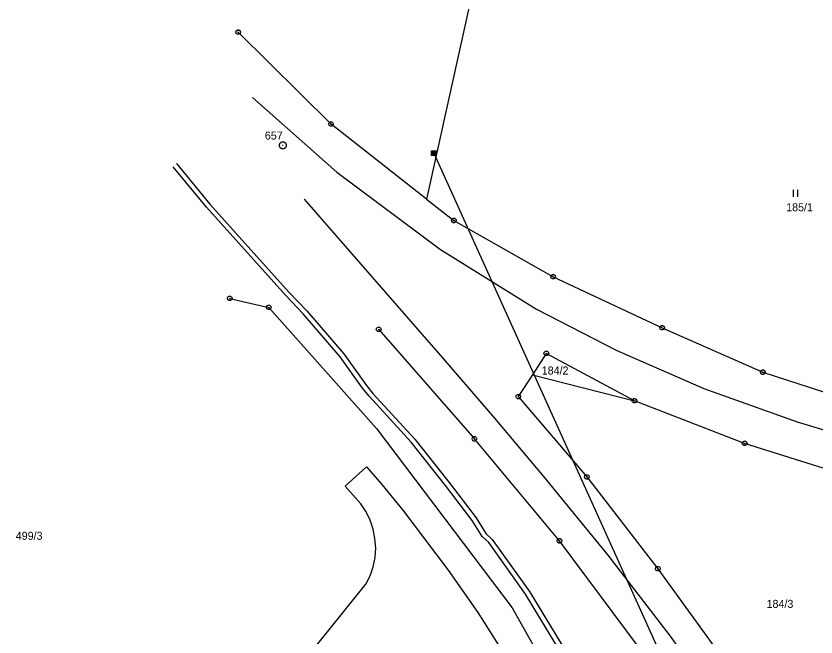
# Model space of a CAD drawing. Extents: x -755359 to -754474, y -1162585 to -1161655.
# Drawn here: x -755334.3 to -755164.4, y -1162276.2 to -1162144.3 of the extents above; entities that cross this region are included whole.
import ezdxf

# ---------------------------------------------------------------- set-up
doc = ezdxf.new("R2010")
doc.units = 0
for name, color, linetype in [('Vrstva 1', 7, 'Continuous'), ('Vrstva 13', 7, 'Continuous'), ('Vrstva 2', 7, 'Continuous'), ('Vrstva 3', 7, 'Continuous'), ('Vrstva 6', 7, 'Continuous'), ('Vrstva 8', 7, 'Continuous')]:
    doc.layers.add(name, color=color, linetype=linetype)

msp = doc.modelspace()

# ---------------------------------------------------------------- linework, layer by layer
at = {"layer": 'Vrstva 1'}
for p, q in [((-755230.33, -1162107.53), (-755247.11, -1162183.21)), ((-755267.37, -1162167.29), (-755287.08, -1162147.76)), ((-755287.08, -1162147.76), (-755287.08, -1162147.76)), ((-755247.11, -1162183.21), (-755267.37, -1162167.29)), ((-755247.11, -1162183.21), (-755241.3, -1162187.77)), ((-755241.3, -1162187.77), (-755220.18, -1162199.71)), ((-755220.18, -1162199.71), (-755197.03, -1162210.54)), ((-755288.88, -1162204.3), (-755288.88, -1162204.3)), ((-755288.88, -1162204.3), (-755280.59, -1162206.21)), ((-755257.72, -1162231.95), (-755280.59, -1162206.21)), ((-755280.59, -1162206.21), (-755280.59, -1162206.21)), ((-755257.25, -1162210.88), (-755257.25, -1162210.88)), ((-755257.25, -1162210.88), (-755255.8, -1162212.54)), ((-755197.03, -1162210.54), (-755175.66, -1162219.97)), ((-755255.8, -1162212.54), (-755236.92, -1162234.12)), ((-755221.65, -1162215.97), (-755224.59, -1162220.51)), ((-755202.91, -1162226.05), (-755221.65, -1162215.97)), ((-755224.59, -1162220.51), (-755227.6, -1162225.16)), ((-755224.59, -1162220.51), (-755202.91, -1162226.05)), ((-755175.66, -1162219.97), (-755153.09, -1162227.31)), ((-755227.6, -1162225.16), (-755213.03, -1162242.21)), ((-755179.53, -1162235.08), (-755202.91, -1162226.05)), ((-755257.72, -1162231.95), (-755228.92, -1162270)), ((-755218.86, -1162255.78), (-755236.92, -1162234.12)), ((-755156.59, -1162242.36), (-755179.53, -1162235.08)), ((-755264.36, -1162244.17), (-755259.86, -1162240.09)), ((-755259.86, -1162240.09), (-755256.55, -1162243.81)), ((-755213.03, -1162242.21), (-755197.95, -1162261.69)), ((-755261.07, -1162247.95), (-755264.36, -1162244.17)), ((-755256.55, -1162243.81), (-755252.15, -1162249.27)), ((-755259.94, -1162249.61), (-755261.07, -1162247.95)), ((-755259.06, -1162251.4), (-755259.94, -1162249.61)), ((-755252.15, -1162249.27), (-755242.47, -1162262.02)), ((-755258.42, -1162253.32), (-755259.06, -1162251.4)), ((-755258.04, -1162255.29), (-755258.42, -1162253.32)), ((-755257.86, -1162257.3), (-755258.04, -1162255.29)), ((-755201.65, -1162278.82), (-755218.86, -1162255.78)), ((-755258.01, -1162259.3), (-755257.86, -1162257.3)), ((-755258.42, -1162261.28), (-755258.01, -1162259.3)), ((-755259.05, -1162263.18), (-755258.42, -1162261.28)), ((-755242.47, -1162262.02), (-755236.16, -1162271.02)), ((-755197.95, -1162261.69), (-755179.66, -1162287.01)), ((-755259.96, -1162264.99), (-755259.05, -1162263.18)), ((-755273.15, -1162281.3), (-755259.96, -1162264.99)), ((-755228.92, -1162270), (-755211.8, -1162300.42)), ((-755236.16, -1162271.02), (-755230.79, -1162279.46))]:
    msp.add_line(p, q, dxfattribs=at)
at = {"layer": 'Vrstva 13'}
for p, q in [((-755293.84, -1162184.94), (-755300.91, -1162176.35)), ((-755300.91, -1162176.35), (-755300.91, -1162176.35)), ((-755300.17, -1162175.67), (-755300.17, -1162175.67)), ((-755300.17, -1162175.67), (-755293.08, -1162184.3)), ((-755276.95, -1162203.71), (-755293.84, -1162184.94)), ((-755293.08, -1162184.3), (-755276.23, -1162203.03)), ((-755273.27, -1162207.6), (-755276.95, -1162203.71)), ((-755276.23, -1162203.03), (-755272.53, -1162206.94)), ((-755265.46, -1162216.72), (-755273.27, -1162207.6)), ((-755272.53, -1162206.94), (-755264.68, -1162216.1)), ((-755264.68, -1162216.1), (-755259.87, -1162222.77)), ((-755260.66, -1162223.38), (-755265.46, -1162216.72)), ((-755259.87, -1162222.77), (-755258.46, -1162224.49)), ((-755259.22, -1162225.15), (-755260.66, -1162223.38)), ((-755258.46, -1162224.49), (-755249.58, -1162234.18)), ((-755250.34, -1162234.82), (-755259.22, -1162225.15)), ((-755243.05, -1162244.02), (-755250.34, -1162234.82)), ((-755249.58, -1162234.18), (-755242.27, -1162243.4)), ((-755242.27, -1162243.4), (-755236.58, -1162250.87)), ((-755237.41, -1162251.44), (-755243.05, -1162244.02)), ((-755235.27, -1162254.83), (-755237.41, -1162251.44)), ((-755236.58, -1162250.87), (-755234.49, -1162254.19)), ((-755233.89, -1162256.15), (-755235.27, -1162254.83)), ((-755234.49, -1162254.19), (-755233.13, -1162255.49)), ((-755226.08, -1162267.13), (-755233.89, -1162256.15)), ((-755233.13, -1162255.49), (-755225.24, -1162266.57)), ((-755216.34, -1162283.1), (-755226.08, -1162267.13)), ((-755225.24, -1162266.57), (-755215.46, -1162282.62))]:
    msp.add_line(p, q, dxfattribs=at)
at = {"layer": 'Vrstva 3'}
for p, q in [((-755169.21, -1162181.25), (-755169.21, -1162182.75)), ((-755168.21, -1162182.75), (-755168.21, -1162181.25))]:
    msp.add_line(p, q, dxfattribs=at)
at = {"layer": 'Vrstva 6'}
for p, q in [((-755284.05, -1162161.63), (-755284.05, -1162161.63)), ((-755284.05, -1162161.63), (-755266.15, -1162177.51)), ((-755245.56, -1162173.47), (-755245.56, -1162173.47)), ((-755245.56, -1162173.47), (-755187.29, -1162302.18)), ((-755266.15, -1162177.51), (-755244.12, -1162193.92)), ((-755273.1, -1162183.25), (-755273.1, -1162183.25)), ((-755273.1, -1162183.25), (-755243.68, -1162216.91)), ((-755244.12, -1162193.92), (-755223.71, -1162206.57)), ((-755223.71, -1162206.57), (-755206.83, -1162215.32)), ((-755206.83, -1162215.32), (-755188.2, -1162223.46)), ((-755243.68, -1162216.91), (-755232.65, -1162229.71)), ((-755188.2, -1162223.46), (-755168.39, -1162230.54)), ((-755232.65, -1162229.71), (-755222.28, -1162242.12)), ((-755168.39, -1162230.54), (-755153.14, -1162235.03)), ((-755222.28, -1162242.12), (-755208.59, -1162258.85)), ((-755208.59, -1162258.85), (-755195.32, -1162276.05)), ((-755195.32, -1162276.05), (-755182.68, -1162293.67))]:
    msp.add_line(p, q, dxfattribs=at)
msp.add_lwpolyline([(-755246.06, -1162172.97), (-755245.06, -1162172.97), (-755245.06, -1162173.97), (-755246.06, -1162173.97), (-755246.06, -1162172.97), (-755246, -1162173.03), (-755245.12, -1162173.03), (-755245.12, -1162173.11), (-755246, -1162173.11), (-755246, -1162173.19), (-755245.12, -1162173.19), (-755245.12, -1162173.27), (-755246, -1162173.27), (-755246, -1162173.35), (-755245.12, -1162173.35), (-755245.12, -1162173.43), (-755246, -1162173.43), (-755246, -1162173.51), (-755245.12, -1162173.51), (-755245.12, -1162173.59), (-755246, -1162173.59), (-755246, -1162173.67), (-755245.12, -1162173.67), (-755245.12, -1162173.75), (-755246, -1162173.75), (-755246, -1162173.83), (-755245.12, -1162173.83), (-755245.12, -1162173.91), (-755246, -1162173.91)], dxfattribs=at)
at = {"layer": 'Vrstva 8'}
for p, q in [((-755287.2, -1162147.76), (-755286.96, -1162147.76)), ((-755267.49, -1162167.29), (-755267.25, -1162167.29)), ((-755277.65, -1162171.78), (-755277.55, -1162171.78)), ((-755241.42, -1162187.77), (-755241.18, -1162187.77)), ((-755220.3, -1162199.71), (-755220.06, -1162199.71)), ((-755289, -1162204.3), (-755288.76, -1162204.3)), ((-755280.71, -1162206.21), (-755280.47, -1162206.21)), ((-755257.37, -1162210.88), (-755257.13, -1162210.88)), ((-755197.15, -1162210.54), (-755196.91, -1162210.54)), ((-755221.77, -1162215.97), (-755221.53, -1162215.97)), ((-755175.78, -1162219.97), (-755175.54, -1162219.97)), ((-755227.72, -1162225.16), (-755227.48, -1162225.16)), ((-755203.03, -1162226.05), (-755202.79, -1162226.05)), ((-755237.04, -1162234.12), (-755236.8, -1162234.12)), ((-755179.65, -1162235.08), (-755179.41, -1162235.08)), ((-755213.15, -1162242.21), (-755212.91, -1162242.21)), ((-755218.98, -1162255.78), (-755218.74, -1162255.78)), ((-755198.07, -1162261.69), (-755197.83, -1162261.69))]:
    msp.add_line(p, q, dxfattribs=at)
for points in [[(-755286.93, -1162147.28), (-755286.68, -1162147.46), (-755286.58, -1162147.75), (-755286.68, -1162148.04), (-755286.93, -1162148.22), (-755287.24, -1162148.22), (-755287.49, -1162148.04), (-755287.59, -1162147.75), (-755287.49, -1162147.46), (-755287.24, -1162147.28)], [(-755267.22, -1162166.81), (-755266.97, -1162166.99), (-755266.87, -1162167.28), (-755266.97, -1162167.57), (-755267.22, -1162167.75), (-755267.53, -1162167.75), (-755267.78, -1162167.57), (-755267.88, -1162167.28), (-755267.78, -1162166.99), (-755267.53, -1162166.81)], [(-755277.41, -1162171.06), (-755277.07, -1162171.25), (-755276.88, -1162171.59), (-755276.88, -1162171.98), (-755277.07, -1162172.32), (-755277.41, -1162172.51), (-755277.8, -1162172.51), (-755278.14, -1162172.32), (-755278.33, -1162171.98), (-755278.33, -1162171.59), (-755278.14, -1162171.25), (-755277.8, -1162171.06)], [(-755241.15, -1162187.29), (-755240.9, -1162187.47), (-755240.8, -1162187.76), (-755240.9, -1162188.05), (-755241.15, -1162188.23), (-755241.46, -1162188.23), (-755241.71, -1162188.05), (-755241.81, -1162187.76), (-755241.71, -1162187.47), (-755241.46, -1162187.29)], [(-755220.03, -1162199.23), (-755219.78, -1162199.41), (-755219.68, -1162199.7), (-755219.78, -1162199.99), (-755220.03, -1162200.17), (-755220.34, -1162200.17), (-755220.59, -1162199.99), (-755220.69, -1162199.7), (-755220.59, -1162199.41), (-755220.34, -1162199.23)], [(-755288.73, -1162203.82), (-755288.48, -1162204), (-755288.38, -1162204.29), (-755288.48, -1162204.58), (-755288.73, -1162204.76), (-755289.04, -1162204.76), (-755289.29, -1162204.58), (-755289.39, -1162204.29), (-755289.29, -1162204), (-755289.04, -1162203.82)], [(-755280.44, -1162205.73), (-755280.19, -1162205.91), (-755280.09, -1162206.2), (-755280.19, -1162206.49), (-755280.44, -1162206.67), (-755280.75, -1162206.67), (-755281, -1162206.49), (-755281.1, -1162206.2), (-755281, -1162205.91), (-755280.75, -1162205.73)], [(-755257.1, -1162210.4), (-755256.85, -1162210.58), (-755256.75, -1162210.87), (-755256.85, -1162211.16), (-755257.1, -1162211.34), (-755257.41, -1162211.34), (-755257.66, -1162211.16), (-755257.76, -1162210.87), (-755257.66, -1162210.58), (-755257.41, -1162210.4)], [(-755196.88, -1162210.06), (-755196.63, -1162210.24), (-755196.53, -1162210.53), (-755196.63, -1162210.82), (-755196.88, -1162211), (-755197.19, -1162211), (-755197.44, -1162210.82), (-755197.54, -1162210.53), (-755197.44, -1162210.24), (-755197.19, -1162210.06)], [(-755221.5, -1162215.49), (-755221.25, -1162215.67), (-755221.15, -1162215.96), (-755221.25, -1162216.25), (-755221.5, -1162216.43), (-755221.81, -1162216.43), (-755222.06, -1162216.25), (-755222.16, -1162215.96), (-755222.06, -1162215.67), (-755221.81, -1162215.49)], [(-755175.51, -1162219.49), (-755175.26, -1162219.67), (-755175.16, -1162219.96), (-755175.26, -1162220.25), (-755175.51, -1162220.43), (-755175.82, -1162220.43), (-755176.07, -1162220.25), (-755176.17, -1162219.96), (-755176.07, -1162219.67), (-755175.82, -1162219.49)], [(-755227.45, -1162224.68), (-755227.2, -1162224.86), (-755227.1, -1162225.15), (-755227.2, -1162225.44), (-755227.45, -1162225.62), (-755227.76, -1162225.62), (-755228.01, -1162225.44), (-755228.11, -1162225.15), (-755228.01, -1162224.86), (-755227.76, -1162224.68)], [(-755202.76, -1162225.57), (-755202.51, -1162225.75), (-755202.41, -1162226.04), (-755202.51, -1162226.33), (-755202.76, -1162226.51), (-755203.07, -1162226.51), (-755203.32, -1162226.33), (-755203.42, -1162226.04), (-755203.32, -1162225.75), (-755203.07, -1162225.57)], [(-755236.77, -1162233.64), (-755236.52, -1162233.82), (-755236.42, -1162234.11), (-755236.52, -1162234.4), (-755236.77, -1162234.58), (-755237.08, -1162234.58), (-755237.33, -1162234.4), (-755237.43, -1162234.11), (-755237.33, -1162233.82), (-755237.08, -1162233.64)], [(-755179.38, -1162234.6), (-755179.13, -1162234.78), (-755179.03, -1162235.07), (-755179.13, -1162235.36), (-755179.38, -1162235.54), (-755179.69, -1162235.54), (-755179.94, -1162235.36), (-755180.04, -1162235.07), (-755179.94, -1162234.78), (-755179.69, -1162234.6)], [(-755212.88, -1162241.73), (-755212.63, -1162241.91), (-755212.53, -1162242.2), (-755212.63, -1162242.49), (-755212.88, -1162242.67), (-755213.19, -1162242.67), (-755213.44, -1162242.49), (-755213.54, -1162242.2), (-755213.44, -1162241.91), (-755213.19, -1162241.73)], [(-755218.71, -1162255.3), (-755218.46, -1162255.48), (-755218.36, -1162255.77), (-755218.46, -1162256.06), (-755218.71, -1162256.24), (-755219.02, -1162256.24), (-755219.27, -1162256.06), (-755219.37, -1162255.77), (-755219.27, -1162255.48), (-755219.02, -1162255.3)], [(-755197.8, -1162261.21), (-755197.55, -1162261.39), (-755197.45, -1162261.68), (-755197.55, -1162261.97), (-755197.8, -1162262.15), (-755198.11, -1162262.15), (-755198.36, -1162261.97), (-755198.46, -1162261.68), (-755198.36, -1162261.39), (-755198.11, -1162261.21)]]:
    msp.add_lwpolyline(points, close=True, dxfattribs=at)

# ---------------------------------------------------------------- texts
at = {"layer": 'Vrstva 2'}
for s, p in [('185/1', (-755170.717, -1162185.8)), ('184/2', (-755222.627, -1162220.46)), ('499/3', (-755334.323, -1162255.55)), ('184/3', (-755174.877, -1162270.01))]:
    msp.add_text(s, height=1.7, dxfattribs=at).set_placement(p)
at = {"layer": 'Vrstva 8'}
msp.add_text('657', height=1.7, dxfattribs=at).set_placement((-755281.423, -1162170.58))

doc.saveas('drawing.dxf')
